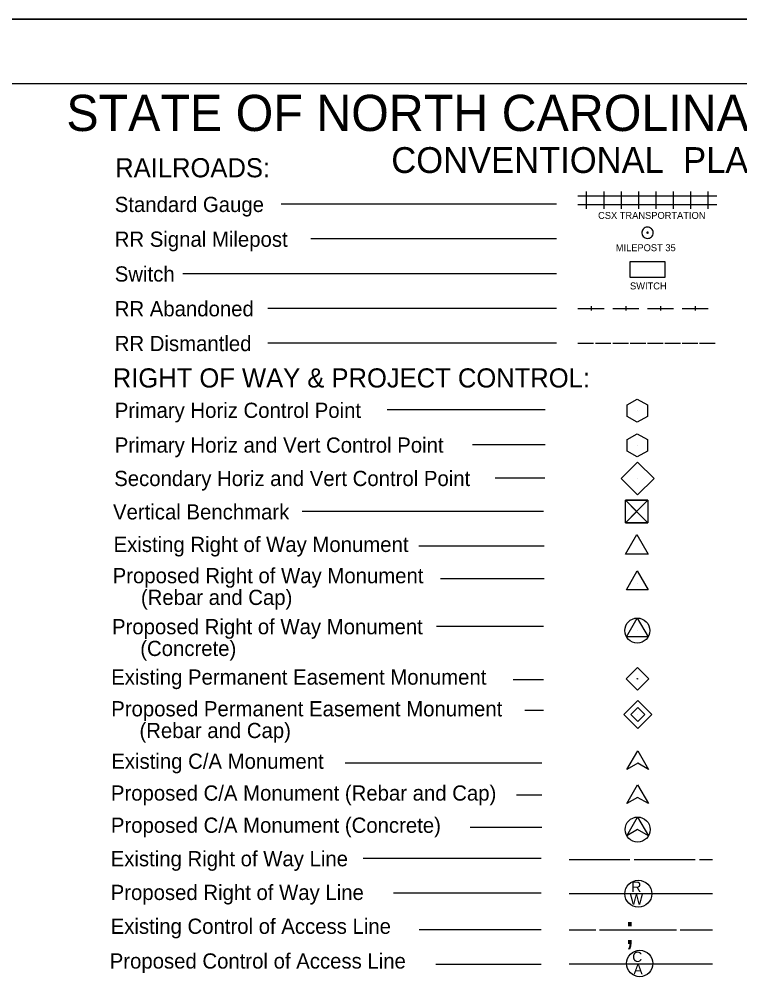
# Model space of a CAD drawing. Extents: x 754056.72 to 754059.56, y 596603.78 to 596605.61.
# Drawn here: x 754057.422 to 754058.119, y 596604.682 to 596605.612 of the extents above; entities that cross this region are included whole.
import ezdxf

# ---------------------------------------------------------------- set-up
doc = ezdxf.new("R2010")
doc.units = 0
for name, color, linetype in [('P_RDY_ROW_Permanent_Easement', 7, 'Continuous'), ('Sheet_Plan', 7, 'Continuous'), ('Sheet_Plot_Border_Outside_CELL', 7, 'Continuous'), ('Sheet_Symbology', 7, 'Continuous'), ('z - Construction', 7, 'Continuous')]:
    doc.layers.add(name, color=color, linetype=linetype)

msp = doc.modelspace()

# ---------------------------------------------------------------- linework, layer by layer
at = {"layer": 'P_RDY_ROW_Permanent_Easement'}
msp.add_line((754058.02064, 596604.93893), (754058.02064, 596604.93893), dxfattribs=at)
for points in [[(754058.02064, 596604.95247), (754058.03418, 596604.93892), (754058.02064, 596604.92539), (754058.0071, 596604.93892)], [(754058.02064, 596604.94569), (754058.02741, 596604.93892), (754058.02064, 596604.93216), (754058.01387, 596604.93892)]]:
    msp.add_lwpolyline(points, close=True, dxfattribs=at)
at = {"layer": 'Sheet_Plan'}
msp.add_line((754059.49567, 596605.54909), (754056.78733, 596605.54909), dxfattribs=at)
at = {"layer": 'Sheet_Plot_Border_Outside_CELL'}
msp.add_lwpolyline([(754056.72484, 596605.61159), (754059.55817, 596605.61159), (754059.55817, 596603.77826), (754056.72484, 596603.77826)], close=True, dxfattribs=at)
at = {"layer": 'Sheet_Symbology'}
for p, q in [((754057.9628, 596605.4407), (754057.97961, 596605.4407)), ((754057.9712, 596605.42808), (754057.9712, 596605.4449)), ((754057.97961, 596605.4407), (754057.99643, 596605.4407)), ((754057.98802, 596605.42808), (754057.98802, 596605.4449)), ((754057.99643, 596605.4407), (754058.01324, 596605.4407)), ((754058.00484, 596605.42808), (754058.00484, 596605.4449)), ((754058.01324, 596605.4407), (754058.03006, 596605.4407)), ((754058.02165, 596605.42808), (754058.02165, 596605.4449)), ((754058.03006, 596605.4407), (754058.04687, 596605.4407)), ((754058.03847, 596605.42808), (754058.03847, 596605.4449)), ((754058.04687, 596605.4407), (754058.06369, 596605.4407)), ((754058.05528, 596605.42808), (754058.05528, 596605.4449)), ((754058.06369, 596605.4407), (754058.08051, 596605.4407)), ((754058.0721, 596605.42808), (754058.0721, 596605.4449)), ((754058.08051, 596605.4407), (754058.09732, 596605.4407)), ((754058.08891, 596605.42808), (754058.08891, 596605.4449)), ((754057.94196, 596605.43269), (754057.67558, 596605.43269)), ((754057.9628, 596605.43229), (754057.97961, 596605.43229)), ((754057.97961, 596605.43229), (754057.99643, 596605.43229)), ((754057.99643, 596605.43229), (754058.01324, 596605.43229)), ((754058.01324, 596605.43229), (754058.03006, 596605.43229)), ((754058.03006, 596605.43229), (754058.04687, 596605.43229)), ((754058.04687, 596605.43229), (754058.06369, 596605.43229)), ((754058.06369, 596605.43229), (754058.08051, 596605.43229)), ((754058.08051, 596605.43229), (754058.09732, 596605.43229)), ((754057.94196, 596605.39906), (754057.7044, 596605.39906)), ((754057.94196, 596605.36543), (754057.58057, 596605.36543)), ((754057.94196, 596605.33179), (754057.66254, 596605.33179)), ((754057.9628, 596605.33179), (754057.98802, 596605.33179)), ((754057.97541, 596605.3339), (754057.97541, 596605.32969)), ((754057.99643, 596605.33179), (754058.02165, 596605.33179)), ((754058.00904, 596605.3339), (754058.00904, 596605.32969)), ((754058.03006, 596605.33179), (754058.05528, 596605.33179)), ((754058.04267, 596605.3339), (754058.04267, 596605.32969)), ((754058.06369, 596605.33179), (754058.08891, 596605.33179)), ((754058.0763, 596605.3339), (754058.0763, 596605.32969)), ((754057.94196, 596605.29816), (754057.66254, 596605.29816)), ((754057.94196, 596605.29816), (754057.66254, 596605.29816)), ((754057.9628, 596605.29816), (754057.97793, 596605.29816)), ((754057.97961, 596605.29816), (754057.99475, 596605.29816)), ((754057.99643, 596605.29816), (754058.01156, 596605.29816)), ((754058.01324, 596605.29816), (754058.02838, 596605.29816)), ((754058.03006, 596605.29816), (754058.04519, 596605.29816)), ((754058.04687, 596605.29816), (754058.06201, 596605.29816)), ((754058.06369, 596605.29816), (754058.07882, 596605.29816)), ((754058.08051, 596605.29816), (754058.09564, 596605.29816)), ((754057.93118, 596605.2336), (754057.77811, 596605.2336)), ((754058.02019, 596605.23298), (754058.02019, 596605.23298)), ((754057.93118, 596605.19997), (754057.86069, 596605.19997)), ((754058.02017, 596605.1994), (754058.02017, 596605.1994)), ((754057.93065, 596605.16768), (754057.88264, 596605.16768)), ((754058.0204, 596605.16733), (754058.0204, 596605.16733)), ((754057.92949, 596605.13536), (754057.69602, 596605.13536)), ((754058.01956, 596605.13538), (754058.01956, 596605.13538)), ((754057.93002, 596605.10176), (754057.80886, 596605.10176)), ((754057.93019, 596605.07017), (754057.82975, 596605.07017)), ((754058.02018, 596605.06577), (754058.02018, 596605.06577)), ((754057.92934, 596605.02409), (754057.82595, 596605.02409)), ((754058.02021, 596605.02027), (754058.02021, 596605.02027)), ((754057.92947, 596604.97247), (754057.89996, 596604.97247)), ((754058.02034, 596604.97358), (754058.02034, 596604.97358)), ((754057.92947, 596604.94284), (754057.91131, 596604.94284)), ((754058.0101, 596604.88583), (754058.02061, 596604.90399)), ((754058.02061, 596604.90399), (754058.03112, 596604.88583)), ((754057.92781, 596604.89203), (754057.73739, 596604.89203)), ((754058.02061, 596604.89188), (754058.0101, 596604.88583)), ((754058.03112, 596604.88583), (754058.02061, 596604.89188)), ((754058.01005, 596604.85285), (754058.02055, 596604.87101)), ((754058.02055, 596604.87101), (754058.03106, 596604.85285)), ((754057.92797, 596604.86087), (754057.90347, 596604.86087)), ((754058.02055, 596604.8589), (754058.01005, 596604.85285)), ((754058.03106, 596604.85285), (754058.02055, 596604.8589)), ((754058.01005, 596604.82173), (754058.02055, 596604.83989)), ((754058.02055, 596604.83989), (754058.03106, 596604.82173)), ((754057.92797, 596604.82975), (754057.85836, 596604.82975)), ((754058.02055, 596604.82778), (754058.01005, 596604.82173)), ((754058.03106, 596604.82173), (754058.02055, 596604.82778)), ((754057.92723, 596604.79985), (754057.75485, 596604.79985)), ((754057.95419, 596604.79888), (754058.01304, 596604.79888)), ((754058.01725, 596604.79888), (754058.0761, 596604.79888)), ((754058.08031, 596604.79888), (754058.09292, 596604.79888)), ((754057.92723, 596604.76622), (754057.78423, 596604.76622)), ((754057.95419, 596604.76601), (754058.09292, 596604.76601)), ((754057.92723, 596604.7307), (754057.80912, 596604.7307)), ((754057.95419, 596604.7307), (754057.98019, 596604.7307)), ((754057.98355, 596604.7307), (754058.05824, 596604.7307)), ((754058.0616, 596604.7307), (754058.09292, 596604.7307)), ((754057.92723, 596604.69737), (754057.82514, 596604.69737)), ((754057.95419, 596604.69801), (754058.09292, 596604.69801))]:
    msp.add_line(p, q, dxfattribs=at)
for points in [[(754058.03554, 596605.40504), (754058.03543, 596605.40613), (754058.03511, 596605.40723), (754058.03456, 596605.40821), (754058.03379, 596605.40898), (754058.03292, 596605.40963), (754058.03194, 596605.41018), (754058.03095, 596605.4104), (754058.02975, 596605.4105), (754058.02866, 596605.41029), (754058.02768, 596605.40996), (754058.0267, 596605.40941), (754058.02593, 596605.40865), (754058.02527, 596605.40767), (754058.02484, 596605.40668), (754058.02462, 596605.40559), (754058.02462, 596605.4045), (754058.02484, 596605.4034), (754058.02527, 596605.40242), (754058.02593, 596605.40144), (754058.0267, 596605.40068), (754058.02768, 596605.40013), (754058.02866, 596605.3998), (754058.02975, 596605.39958), (754058.03095, 596605.39969), (754058.03194, 596605.39991), (754058.03292, 596605.40045), (754058.03379, 596605.40111), (754058.03456, 596605.40188), (754058.03511, 596605.40286), (754058.03543, 596605.40395), (754058.03554, 596605.40504)], [(754058.0303, 596605.4057), (754058.02997, 596605.4057), (754058.02964, 596605.40548), (754058.02943, 596605.40515), (754058.02953, 596605.40482), (754058.02975, 596605.4045), (754058.03008, 596605.40439), (754058.03041, 596605.4045), (754058.03062, 596605.40472), (754058.03073, 596605.40515), (754058.03062, 596605.40548), (754058.0303, 596605.4057)], [(754058.02019, 596605.22179), (754058.01044, 596605.22733), (754058.01044, 596605.23852), (754058.02019, 596605.24417), (754058.02994, 596605.23863), (754058.02994, 596605.22733), (754058.02019, 596605.22179)], [(754058.03044, 596605.14626), (754058.00864, 596605.12446), (754058.01954, 596605.13536), (754058.03044, 596605.12446), (754058.00864, 596605.14626)], [(754058.01954, 596605.13536), (754058.03044, 596605.14626), (754058.00864, 596605.14626), (754058.01954, 596605.13536)], [(754058.01954, 596605.13536), (754058.00864, 596605.12446), (754058.03044, 596605.12446), (754058.01954, 596605.13536)], [(754058.00881, 596605.09426), (754058.01973, 596605.11322), (754058.03065, 596605.09426), (754058.00881, 596605.09426)]]:
    msp.add_lwpolyline(points, dxfattribs=at)
for points in [[(754058.01324, 596605.37713), (754058.04687, 596605.37713), (754058.04687, 596605.36183), (754058.01324, 596605.36183)], [(754058.01037, 596605.20508), (754058.02023, 596605.21058), (754058.03009, 596605.20516), (754058.02994, 596605.19385), (754058.02008, 596605.18813), (754058.01037, 596605.19363)], [(754058.00458, 596605.16738), (754058.02048, 596605.18329), (754058.03641, 596605.16735), (754058.02051, 596605.15145)], [(754058.00864, 596605.14626), (754058.03044, 596605.14626), (754058.03044, 596605.12446), (754058.00864, 596605.12446)], [(754058.00967, 596605.05972), (754058.02018, 596605.07788), (754058.03069, 596605.05972)], [(754058.0097, 596605.01421), (754058.02021, 596605.03237), (754058.03072, 596605.01421)], [(754058.00942, 596604.97358), (754058.02034, 596604.9845), (754058.03126, 596604.97358), (754058.02034, 596604.96266)]]:
    msp.add_lwpolyline(points, close=True, dxfattribs=at)
for centre, radius in [((754058.0202, 596605.02026), 0.01211), ((754058.02034, 596604.97358), 0.000212), ((754058.02055, 596604.82778), 0.01211), ((754058.02121, 596604.76566), 0.01304), ((754058.02254, 596604.69819), 0.01275)]:
    msp.add_circle(centre, radius, dxfattribs=at)
at = {"layer": 'z - Construction'}
msp.add_line((754059.55817, 596605.61159), (754056.72484, 596605.61159), dxfattribs=at)

# ---------------------------------------------------------------- texts
at = {"layer": 'Sheet_Symbology'}
for s, height, p in [('STATE OF NORTH CAROLINA, DIVISION OF HIGHWAYS', 0.035, (754057.46774, 596605.50345)), ('CONVENTIONAL  PLAN SHEET SYMBOLS', 0.025, (754057.78215, 596605.46284)), ('RAILROADS:', 0.018497, (754057.51503, 596605.45867)), ('Standard Gauge', 0.0147137, (754057.51457, 596605.42508)), ('CSX TRANSPORTATION', 0.0067262, (754057.98224, 596605.41844)), ('RR Signal Milepost', 0.0147137, (754057.51457, 596605.39145)), ('MILEPOST 35', 0.0067262, (754057.99937, 596605.3872)), ('Switch', 0.014714, (754057.51457, 596605.35782)), ('SWITCH', 0.006726, (754058.01316, 596605.35021)), ('RR Abandoned', 0.0147137, (754057.51457, 596605.32419)), ('RR Dismantled', 0.0147137, (754057.51457, 596605.29055)), ('RIGHT OF WAY & PROJECT CONTROL:', 0.0184972, (754057.51266, 596605.25536)), ('Primary Horiz Control Point', 0.0147137, (754057.51457, 596605.22595)), ('Primary Horiz and Vert Control Point', 0.0147137, (754057.51457, 596605.19232)), ('Secondary Horiz and Vert Control Point', 0.0147137, (754057.51405, 596605.16003)), ('Vertical Benchmark', 0.0147137, (754057.51289, 596605.12771)), ('Existing Right of Way Monument', 0.0147137, (754057.51341, 596605.09624)), ('Proposed Right of Way Monument', 0.0147137, (754057.51254, 596605.06602)), ('     (Rebar and Cap)', 0.0147137, (754057.51254, 596605.045)), ('Proposed Right of Way Monument', 0.0147137, (754057.51191, 596605.01666)), ('     (Concrete)', 0.0147137, (754057.51191, 596604.99564)), ('Existing Permanent Easement Monument', 0.0147137, (754057.5111, 596604.96791)), ('Proposed Permanent Easement Monument', 0.0147137, (754057.51116, 596604.93725)), ('     (Rebar and Cap)', 0.0147137, (754057.51116, 596604.91623)), ('Existing C/A Monument', 0.0147137, (754057.5112, 596604.88652)), ('Proposed C/A Monument (Rebar and Cap)', 0.0147137, (754057.51085, 596604.85573)), ('Proposed C/A Monument (Concrete)', 0.0147137, (754057.51085, 596604.82461)), ('Existing Right of Way Line', 0.0147137, (754057.51063, 596604.7922)), ('Proposed Right of Way Line', 0.0147137, (754057.51063, 596604.75962)), ('R', 0.01022, (754058.01437, 596604.7672)), ('W', 0.01022, (754058.01291, 596604.75516)), ('Existing Control of Access Line', 0.0147137, (754057.51063, 596604.72689)), (';', 0.02775, (754058.00765, 596604.71693)), ('Proposed Control of Access Line', 0.0147137, (754057.50971, 596604.69329)), ('C', 0.00999, (754058.01533, 596604.69969)), ('A', 0.00999, (754058.01652, 596604.68769))]:
    msp.add_text(s, height=height, dxfattribs=at).set_placement(p)

doc.saveas('drawing.dxf')
